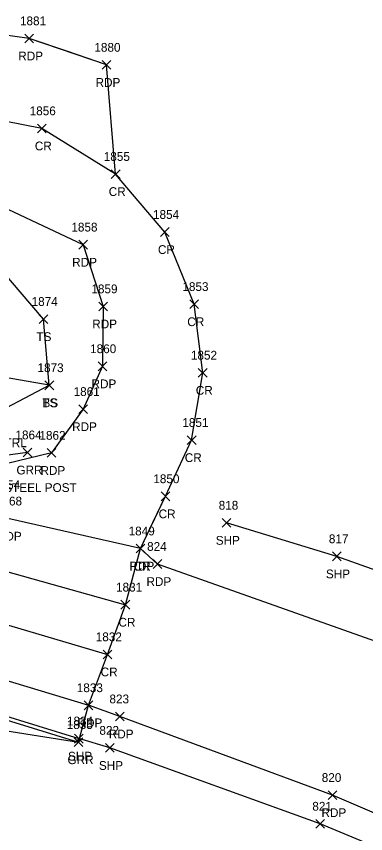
# Model space of a CAD drawing. Extents: x 49137 to 50946, y 9590 to 10709.
# Drawn here: x 50648.8 to 50728.4, y 9974.8 to 10161 of the extents above; entities that cross this region are included whole.
import ezdxf

# ---------------------------------------------------------------- set-up
doc = ezdxf.new("R2010")
doc.units = 0
for name, color, linetype in [('C_A', 7, 'Continuous'), ('C_C', 7, 'Continuous'), ('L_A', 7, 'Continuous'), ('L_I', 7, 'Continuous'), ('L_TIC', 7, 'Continuous'), ('LELB', 7, 'Continuous'), ('LSOGP', 7, 'Continuous'), ('P_A', 7, 'Continuous'), ('P_I', 7, 'Continuous'), ('P_TIC', 7, 'Continuous'), ('PET', 7, 'Continuous'), ('PRC', 7, 'Continuous'), ('PSP', 7, 'Continuous'), ('R_A', 7, 'Continuous'), ('R_C', 7, 'Continuous'), ('R_I', 7, 'Continuous'), ('R_TIC', 7, 'Continuous'), ('RGR', 7, 'Continuous')]:
    doc.layers.add(name, color=color, linetype=linetype)

msp = doc.modelspace()

# ---------------------------------------------------------------- linework, layer by layer
at = {"layer": 'L_TIC'}
for points in [[(50653.98, 10091.07), (50655.98, 10093.07)], [(50655.98, 10091.07), (50653.98, 10093.07)], [(50655.33, 10075.99), (50657.33, 10077.99)], [(50657.33, 10075.99), (50655.33, 10077.99)], [(50655.33, 10075.99), (50657.33, 10077.99)], [(50657.33, 10075.99), (50655.33, 10077.99)]]:
    msp.add_lwpolyline(points, dxfattribs=at)
at = {"layer": 'LELB'}
for points in [[(50615.03, 10068.17), (50632.48, 10066.93), (50640.92, 10068.93), (50656.33, 10076.99), (50654.98, 10092.07), (50644.74, 10103.97), (50625.3, 10115.54), (50585.86, 10113.5), (50533.21, 10111.61), (50454.37, 10111.29)], [(50656.33, 10076.99), (50615.69, 10084.11), (50585.23, 10087.97), (50578.18, 10088.24), (50532.06, 10091.89), (50499.01, 10096.85), (50452.63, 10097.84), (50403.29, 10103.36), (50360.44, 10105.85), (50327.92, 10107.02), (50280.05, 10107.28), (50236.47, 10108.2), (50190.71, 10107.88), (50147.64, 10108.13), (50115.13, 10105.8), (50083.07, 10105.28), (50046.19, 10099.87), (50032.18, 10100.38), (50021.32, 10094.18), (50013.13, 10086.72), (50006.19, 10078.9), (50001.56, 10073.09), (49999.89, 10073.29), (50002.09, 10081.32)]]:
    msp.add_lwpolyline(points, dxfattribs=at)
at = {"layer": 'LSOGP'}
msp.add_lwpolyline([(50623.13, 10001.96), (50662.98, 9995.68), (50665.26, 10004.08), (50669.59, 10015.67), (50673.65, 10027), (50677.09, 10039.79), (50679.94, 10045.74), (50682.79, 10051.69), (50685.76, 10058.1), (50688.74, 10064.5), (50690, 10072.17), (50691.26, 10079.84), (50690.29, 10087.66), (50689.32, 10095.47), (50685.98, 10103.69), (50682.63, 10111.9), (50677.03, 10118.51), (50671.43, 10125.11), (50669.37, 10149.98), (50660.57, 10153), (50651.76, 10156.01), (50643.57, 10157.15)], dxfattribs=at)
at = {"layer": 'P_TIC'}
for points in [[(50650.76, 10155.01), (50652.76, 10157.01)], [(50652.76, 10155.01), (50650.76, 10157.01)], [(50668.37, 10148.98), (50670.37, 10150.98)], [(50670.37, 10148.98), (50668.37, 10150.98)], [(50653.6, 10134.51), (50655.6, 10136.51)], [(50655.6, 10134.51), (50653.6, 10136.51)], [(50670.43, 10124.11), (50672.43, 10126.11)], [(50672.43, 10124.11), (50670.43, 10126.11)], [(50681.64, 10110.9), (50683.64, 10112.9)], [(50683.64, 10110.9), (50681.64, 10112.9)], [(50663.04, 10108.02), (50665.04, 10110.02)], [(50665.04, 10108.02), (50663.04, 10110.02)], [(50663.04, 10108.02), (50665.04, 10110.02)], [(50665.04, 10108.02), (50663.04, 10110.02)], [(50667.61, 10093.95), (50669.61, 10095.95)], [(50669.61, 10093.95), (50667.61, 10095.95)], [(50688.32, 10094.47), (50690.32, 10096.47)], [(50690.32, 10094.47), (50688.32, 10096.47)], [(50667.45, 10080.31), (50669.45, 10082.31)], [(50669.45, 10080.31), (50667.45, 10082.31)], [(50690.26, 10078.84), (50692.26, 10080.84)], [(50692.26, 10078.84), (50690.26, 10080.84)], [(50663.04, 10070.55), (50665.04, 10072.55)], [(50665.04, 10070.55), (50663.04, 10072.55)], [(50687.74, 10063.5), (50689.74, 10065.5)], [(50689.74, 10063.5), (50687.74, 10065.5)], [(50655.82, 10060.58), (50657.82, 10062.58)], [(50657.82, 10060.58), (50655.82, 10062.58)], [(50681.79, 10050.69), (50683.79, 10052.69)], [(50683.79, 10050.69), (50681.79, 10052.69)], [(50695.69, 10044.66), (50697.69, 10046.66)], [(50697.69, 10044.66), (50695.69, 10046.66)], [(50676.1, 10038.79), (50678.1, 10040.79)], [(50678.1, 10038.79), (50676.1, 10040.79)], [(50676.1, 10038.79), (50678.1, 10040.79)], [(50678.1, 10038.79), (50676.1, 10040.79)], [(50720.79, 10037.01), (50722.79, 10039.01)], [(50722.79, 10037.01), (50720.79, 10039.01)], [(50679.97, 10035.27), (50681.97, 10037.27)], [(50681.97, 10035.27), (50679.97, 10037.27)], [(50672.65, 10026), (50674.65, 10028)], [(50674.65, 10026), (50672.65, 10028)], [(50668.59, 10014.68), (50670.59, 10016.68)], [(50670.59, 10014.68), (50668.59, 10016.68)], [(50664.27, 10003.08), (50666.27, 10005.08)], [(50666.27, 10003.08), (50664.27, 10005.08)], [(50671.38, 10000.53), (50673.38, 10002.53)], [(50673.38, 10000.53), (50671.38, 10002.53)], [(50662.04, 9995.49), (50664.04, 9997.49)], [(50664.04, 9995.49), (50662.04, 9997.49)], [(50669.09, 9993.37), (50671.09, 9995.37)], [(50671.09, 9993.37), (50669.09, 9995.37)], [(50719.82, 9982.62), (50721.82, 9984.62)], [(50721.82, 9982.62), (50719.82, 9984.62)], [(50717.01, 9976.08), (50719.01, 9978.08)], [(50719.01, 9976.08), (50717.01, 9978.08)]]:
    msp.add_lwpolyline(points, dxfattribs=at)
at = {"layer": 'PET'}
for points in [[(50669.37, 10149.98), (50651.76, 10156.01), (50635.39, 10158.29), (50616.49, 10156.18), (50587.46, 10148.46), (50573.5, 10145.23), (50560.97, 10144.21), (50549.97, 10143.23), (50500, 10146.8), (50482.82, 10146.6)], [(50664.04, 10109.02), (50639.15, 10120.65), (50622.16, 10120.01), (50585.93, 10117.59), (50533.39, 10115.35), (50500.14, 10114.93), (50454.13, 10114.71), (50404.2, 10117.57), (50361.95, 10120.55), (50329.6, 10122.43), (50280.88, 10124.62), (50237.67, 10126.17), (50191.62, 10126.61), (50146.37, 10126.55), (50115.33, 10126.09), (50083.53, 10125.91), (50041.87, 10123.08), (50027.5, 10119.57), (50014.15, 10112.3), (50001.27, 10099.44), (49993.67, 10082.3), (49991.68, 10072.98), (49993.67, 10063.34)], [(50664.04, 10109.02), (50668.61, 10094.95), (50668.45, 10081.31), (50664.04, 10071.55), (50656.82, 10061.58), (50641.43, 10057.91)], [(50677.1, 10039.79), (50646.91, 10046.61), (50612.99, 10056.93), (50576.26, 10065.94), (50530.63, 10075.88), (50495.53, 10081.77), (50449.66, 10088.73)], [(50478.42, 10048.42), (50499.95, 10044.65), (50530.76, 10039.09), (50563.49, 10032.15), (50601.13, 10023.07), (50628.84, 10015.16), (50665.27, 10004.08)], [(50680.97, 10036.27), (50677.1, 10039.79)], [(50932.97, 9915.72), (50876.92, 9949.5), (50834.93, 9971.52), (50782.09, 9996.99), (50734.35, 10017.3), (50680.97, 10036.27)], [(50672.38, 10001.53), (50665.27, 10004.08)], [(50915.62, 9887.62), (50851.54, 9922.28), (50818.14, 9939.55), (50767.27, 9963.74), (50720.82, 9983.62), (50672.38, 10001.53)]]:
    msp.add_lwpolyline(points, dxfattribs=at)
at = {"layer": 'PRC'}
for points in [[(50677.1, 10039.79), (50682.79, 10051.69), (50688.74, 10064.5), (50691.26, 10079.84), (50689.32, 10095.47), (50682.64, 10111.9), (50671.43, 10125.11), (50654.6, 10135.51), (50632.91, 10139.75), (50616.42, 10136.47), (50551.72, 10128.68), (50528.79, 10127.49), (50496.82, 10130.36), (50455.32, 10129.81)], [(50106.74, 10055.97), (50133.96, 10061.74), (50166.12, 10067.98), (50201.45, 10073.89), (50243.79, 10078.94), (50274, 10081.14), (50312.1, 10082.96), (50354.04, 10082.82), (50390.54, 10081.15), (50416.15, 10078.59), (50439.7, 10076.81), (50481.88, 10071.63), (50505.07, 10068.26), (50535.23, 10062.54), (50570.45, 10054.93), (50608.05, 10045.74), (50637.59, 10037.1), (50673.65, 10027)], [(50479.93, 10060.05), (50503.35, 10056.42), (50534.83, 10050.21), (50567.42, 10043.39), (50604.7, 10034.6), (50633.4, 10026.35), (50669.59, 10015.68)]]:
    msp.add_lwpolyline(points, dxfattribs=at)
at = {"layer": 'PSP'}
for points in [[(50943.04, 9929.02), (50889.9, 9960.93), (50841.59, 9986.57), (50787.61, 10012.13), (50735.23, 10033.21), (50721.79, 10038.01), (50696.69, 10045.66)], [(50477.89, 10041.39), (50498.49, 10037.53), (50529.5, 10032.31), (50561.23, 10025.25), (50599.58, 10015.73), (50625.61, 10008.06), (50663.04, 9996.49)], [(50670.09, 9994.37), (50663.04, 9996.49)], [(50911.3, 9880.1), (50847.15, 9916.49), (50814.65, 9933.82), (50763.96, 9957.97), (50718.01, 9977.08), (50670.09, 9994.37)]]:
    msp.add_lwpolyline(points, dxfattribs=at)
at = {"layer": 'R_TIC'}
for points in [[(50650.36, 10060.68), (50652.36, 10062.68)], [(50652.36, 10060.68), (50650.36, 10062.68)], [(50661.98, 9994.68), (50663.98, 9996.68)], [(50663.98, 9994.68), (50661.98, 9996.68)]]:
    msp.add_lwpolyline(points, dxfattribs=at)
at = {"layer": 'RGR'}
for points in [[(50651.36, 10061.68), (50639.09, 10060.01), (50614.4, 10063.11), (50576.81, 10070.84), (50530.55, 10080.07), (50497.09, 10086.23), (50450.74, 10092.48), (50402.39, 10097.59), (50359.5, 10099.5), (50327.14, 10099.98), (50280.06, 10098.35), (50237.96, 10095.92), (50191.63, 10090.37), (50150.37, 10084.97), (50118.07, 10079.04), (50085.73, 10072.95), (50052.65, 10065.04), (50024.56, 10058.01), (49980.29, 10045.93), (49927.85, 10030.6), (49890.84, 10020.31), (49853.28, 10009.42), (49828.89, 10003.64), (49814.87, 10004.41)], [(50477.66, 10040.11), (50498.48, 10036.57), (50529.17, 10031.31), (50560.62, 10024.25), (50599.39, 10014.52), (50625.76, 10007.17), (50662.98, 9995.68)]]:
    msp.add_lwpolyline(points, dxfattribs=at)

# ---------------------------------------------------------------- texts
at = {"layer": 'C_A'}
for p in [(50640.49, 10062.9), (50640.49, 10062.88)]:
    msp.add_text('HVCTRL', height=2, dxfattribs=at).set_placement(p)
at = {"layer": 'C_C'}
msp.add_text('TIE 5.54', height=2, dxfattribs=at).set_placement((50639.59, 10053.33))
at = {"layer": 'L_A'}
for s, p in [('TS', (50653.39, 10087.07)), ('TS', (50654.74, 10071.99)), ('BS', (50654.77, 10071.99))]:
    msp.add_text(s, height=2, dxfattribs=at).set_placement(p)
at = {"layer": 'L_I'}
for s, p in [('1874', (50652.29, 10095.07)), ('1873', (50653.64, 10079.99)), ('1873', (50653.64, 10079.99))]:
    msp.add_text(s, height=2, dxfattribs=at).set_placement(p)
at = {"layer": 'P_A'}
for s, p in [('RDP', (50649.25, 10151.01)), ('RDP', (50666.86, 10144.98)), ('CR', (50653.03, 10130.51)), ('CR', (50669.86, 10120.11)), ('CR', (50681.07, 10106.9)), ('RDP', (50661.53, 10104.02)), ('RDP', (50661.53, 10104.02)), ('CR', (50687.75, 10090.47)), ('RDP', (50666.1, 10089.95)), ('RDP', (50665.94, 10076.31)), ('CR', (50689.69, 10074.84)), ('RDP', (50661.52, 10066.55)), ('CR', (50687.18, 10059.5)), ('RDP', (50654.31, 10056.58)), ('CR', (50681.22, 10046.69)), ('RDP', (50644.39, 10041.61)), ('SHP', (50694.23, 10040.66)), ('RDP', (50674.58, 10034.79)), ('CR', (50675.53, 10034.79)), ('SHP', (50719.32, 10033.01)), ('RDP', (50678.45, 10031.27)), ('CR', (50672.08, 10022)), ('CR', (50668.02, 10010.68)), ('RDP', (50662.76, 9999.08)), ('RDP', (50669.87, 9996.53)), ('SHP', (50660.58, 9991.49)), ('SHP', (50667.62, 9989.37)), ('RDP', (50718.31, 9978.62))]:
    msp.add_text(s, height=2, dxfattribs=at).set_placement(p)
at = {"layer": 'P_I'}
for s, p in [('1881', (50649.64, 10159.01)), ('1880', (50666.59, 10152.98)), ('1856', (50651.85, 10138.51)), ('1855', (50668.73, 10128.11)), ('1854', (50679.94, 10114.9)), ('1858', (50661.35, 10112.02)), ('1858', (50661.35, 10112.02)), ('1859', (50665.91, 10097.95)), ('1853', (50686.63, 10098.47)), ('1860', (50665.62, 10084.31)), ('1852', (50688.57, 10082.84)), ('1861', (50661.86, 10074.55)), ('1851', (50686.62, 10067.5)), ('1862', (50654.08, 10064.58)), ('1850', (50680.01, 10054.69)), ('1868', (50644.17, 10049.61)), ('818', (50694.9, 10048.66)), ('1849', (50674.39, 10042.79)), ('1849', (50674.39, 10042.79)), ('817', (50719.99, 10041.01)), ('824', (50678.6, 10039.27)), ('1831', (50671.52, 10030)), ('1832', (50666.9, 10018.68)), ('1833', (50662.58, 10007.08)), ('823', (50670.02, 10004.53)), ('1834', (50660.35, 9999.49)), ('822', (50667.73, 9997.37)), ('820', (50718.37, 9986.62)), ('821', (50716.22, 9980.08))]:
    msp.add_text(s, height=2, dxfattribs=at).set_placement(p)
at = {"layer": 'R_A'}
for p in [(50648.84, 10056.68), (50660.47, 9990.68)]:
    msp.add_text('GRR', height=2, dxfattribs=at).set_placement(p)
at = {"layer": 'R_C'}
msp.add_text('SGR W/ STEEL POST', height=2, dxfattribs=at).set_placement((50635.52, 10052.68))
at = {"layer": 'R_I'}
for s, p in [('1864', (50648.62, 10064.68)), ('1835', (50660.29, 9998.68))]:
    msp.add_text(s, height=2, dxfattribs=at).set_placement(p)

doc.saveas('drawing.dxf')
